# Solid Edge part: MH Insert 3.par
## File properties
Author: Dan
Template: metric part.par
Last saved by: Dan
Revision: 2
Application: Solid Edge
Accuracy: 0.990
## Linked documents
FH insert Outer.par
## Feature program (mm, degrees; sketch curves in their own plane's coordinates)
part copy "CopiedPart_1"
delete holes assoc c "unnamed DeleteHolesAssocC 1"
delete faces "unnamed DeleteFaces 1"
sketch for "unnamed Protrusion 1" #1 plane through (0, 0, -36) normal (0, 0, -1) x-axis (-1, 0, 0)
  circle centre (0, 0) radius 53
sketch for "unnamed Protrusion 1" #2 plane through (0, 0, -36) normal (0, 0, -1) x-axis (-1, 0, 0)
  circle centre (0, 0) radius 58
extrude "unnamed Protrusion 1" add to key point along -normal
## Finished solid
Body 1: solid body, 127 faces, 251 edges, 124 vertices.
  Faces by surface: plane 76, cylinder 25, cone 15, sphere 8, spun 2, torus 1
  Edges by curve: line 166, circle 81, intersection 4
Bounding box of the edges (mm; curved faces can reach further): 116.000 x 116.000 x 26.842, from (-58, -58, -36) to (58, 58, -9.1581).
Cylindrical faces by radius (mm): R2.4585 x4, R3 x2, R18.8116 x1, R21.8198 x1, R22.25 x1, R26.8948 x1, R31.4973 x1, R35.75 x1, R38.57 x2, R38.8542 x2, R40.75 x1, R45.5 x1, R53 x1, R55.65 x2, R58 x4
Conical faces (half-angle, radius in mm at the cone's reference point): 2 deg R19.3388 x1, 3 deg R0.55 x8, 59 deg R2.4585 x4, 59 deg R3 x2
Toroidal faces (ring radius, tube radius in mm): R20.4107 r1.015 x1
Spherical faces by radius (mm): R3 x8
Planar faces by outward normal: +x 14, +y 10, +z 17, -x 10, -y 18, -z 5, oblique 2
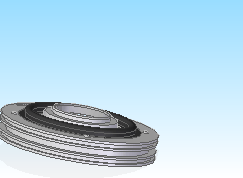
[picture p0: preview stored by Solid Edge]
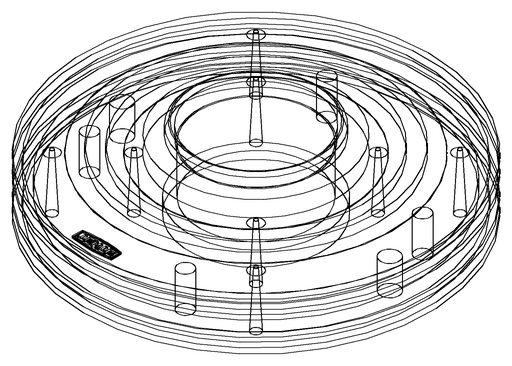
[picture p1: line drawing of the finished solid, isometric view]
